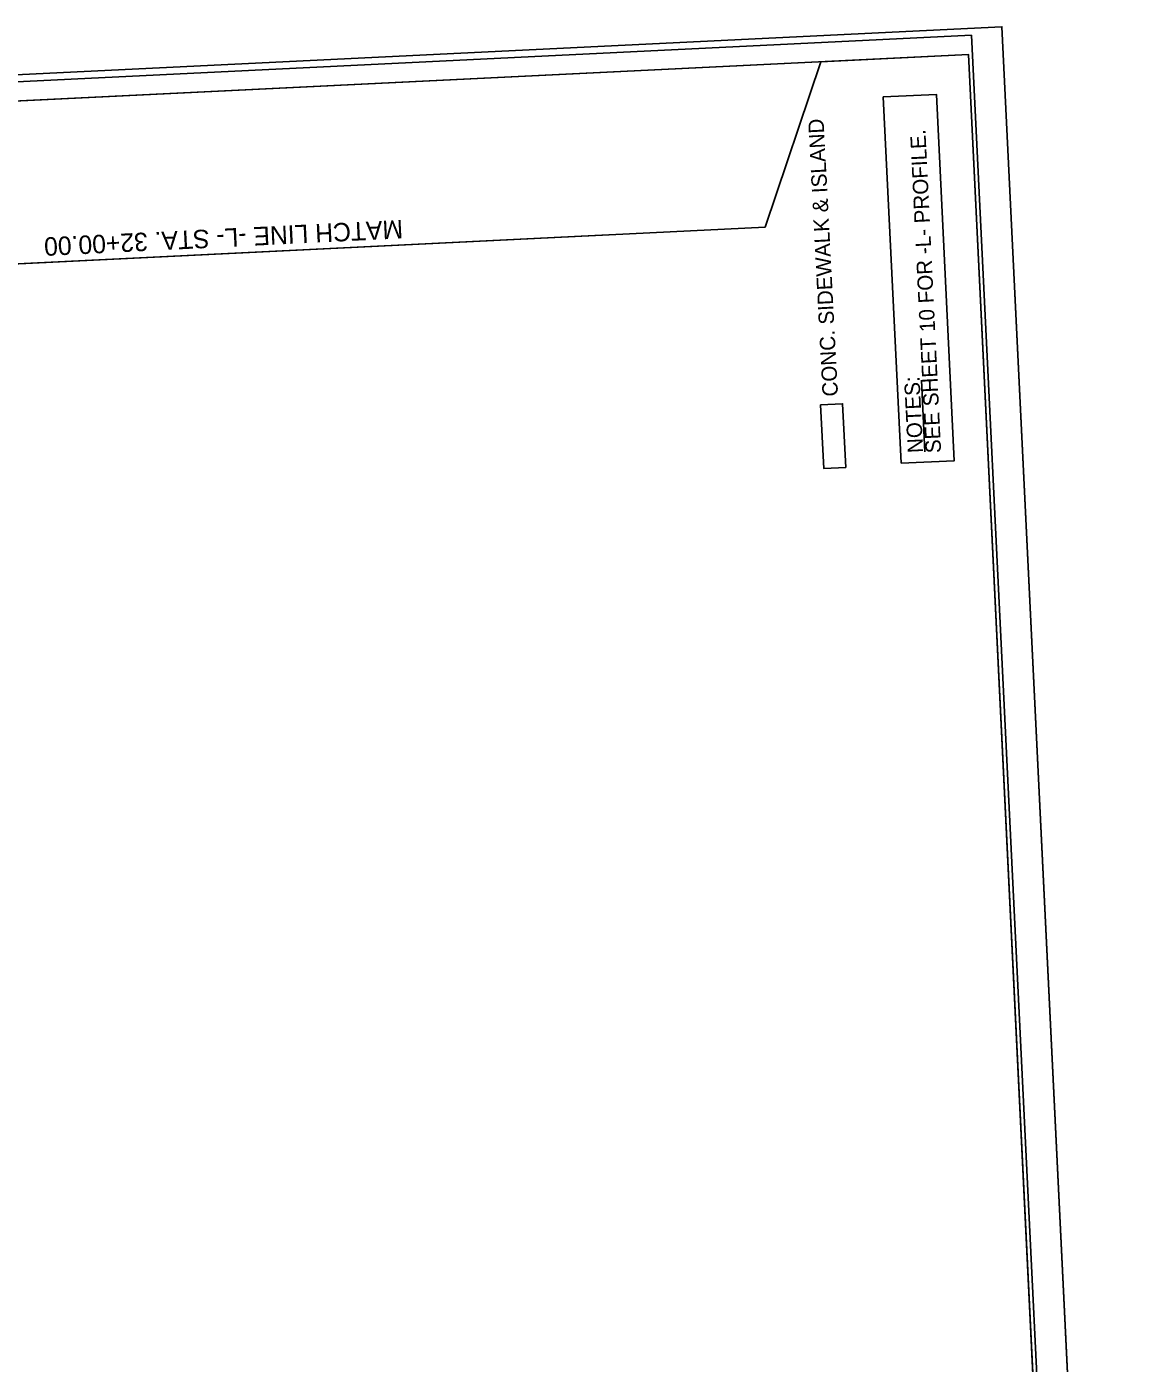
# Model space of a CAD drawing. Extents: x 2368277 to 2369452, y 801942 to 803676.
# Drawn here: x 2368738 to 2369452, y 802809 to 803676 of the extents above; entities that cross this region are included whole.
import ezdxf

# ---------------------------------------------------------------- set-up
doc = ezdxf.new("R2010")
doc.units = 0
for name, color, linetype in [('Old_Level_10', 7, 'Continuous'), ('Old_Level_15', 7, 'Continuous'), ('Old_Level_18', 7, 'Continuous'), ('Old_Level_2', 7, 'Continuous'), ('Old_Level_4', 7, 'Continuous'), ('Old_Level_5', 7, 'Continuous'), ('Old_Level_6', 7, 'Continuous'), ('Old_Level_62', 7, 'Continuous'), ('Old_Level_9', 7, 'Continuous'), ('Plot Label CELL', 7, 'Continuous'), ('Plot Shape CELL', 7, 'Continuous')]:
    doc.layers.add(name, color=color, linetype=linetype)

msp = doc.modelspace()

# ---------------------------------------------------------------- linework, layer by layer
at = {"layer": 'Old_Level_10'}
msp.add_lwpolyline([(2368373.13, 802108.95), (2369421.86, 802160.14), (2369348.77, 803658.36), (2368511.25, 803617.5), (2368522.91, 803378.54), (2368311.67, 803368.23)], close=True, dxfattribs=at)
at = {"layer": 'Old_Level_15'}
msp.add_line((2369452.45, 801994.95), (2369370.42, 803676.45), dxfattribs=at)
at = {"layer": 'Old_Level_18'}
msp.add_line((2369115.17, 803541.41), (2368609.24, 803516.53), dxfattribs=at)
at = {"layer": 'Old_Level_2'}
msp.add_lwpolyline([(2369296.9, 802302.46), (2369299.46, 802249.75), (2368368.59, 802201.94), (2368311.67, 803368.23), (2368522.91, 803378.54), (2368516.4, 803511.97), (2369216.72, 803546.4), (2369252.92, 803653.7), (2369348.77, 803658.37), (2369414.6, 802308.91)], close=True, dxfattribs=at)
msp.add_lwpolyline([(2369296.9, 802302.46), (2369299.46, 802249.75), (2368368.59, 802201.94), (2368311.67, 803368.23), (2368522.91, 803378.54), (2368516.4, 803511.97), (2369216.72, 803546.4), (2369252.92, 803653.7), (2369348.77, 803658.37), (2369414.6, 802308.91)], close=True, dxfattribs=at)
at = {"layer": 'Old_Level_4'}
msp.add_lwpolyline([(2369431.84, 802006.96), (2369350.65, 803670.97), (2368296.92, 803619.57), (2368378.1, 801955.55)], close=True, dxfattribs=at)
at = {"layer": 'Old_Level_5'}
msp.add_lwpolyline([(2369269.06, 803390.47), (2369267.05, 803431.74), (2369252.79, 803431.05), (2369254.81, 803389.77), (2369269.06, 803390.47)], dxfattribs=at)
at = {"layer": 'Old_Level_6'}
msp.add_lwpolyline([(2369452.45, 801994.95), (2369370.42, 803676.45), (2368276.72, 803623.09), (2368358.75, 801941.59)], close=True, dxfattribs=at)
at = {"layer": 'Old_Level_9'}
msp.add_lwpolyline([(2369269.06, 803390.47), (2369267.05, 803431.74), (2369252.79, 803431.05), (2369254.81, 803389.77), (2369269.06, 803390.47)], dxfattribs=at)
at = {"layer": 'Plot Label CELL'}
msp.add_line((2369320.5, 803400.55), (2369318.23, 803446.99), dxfattribs=at)
msp.add_lwpolyline([(2369305, 803393.12), (2369293.4, 803630.86), (2369327.97, 803632.54), (2369339.56, 803394.8)], close=True, dxfattribs=at)
at = {"layer": 'Plot Shape CELL'}
for points in [[(2368300.01, 803607.23), (2368373.1, 802108.98), (2369421.86, 802160.14), (2369348.77, 803658.37)], [(2369421.86, 802160.14), (2368373.13, 802108.95), (2368309.75, 803407.4), (2368459.63, 803414.72), (2368449.9, 803614.52), (2369348.77, 803658.37)]]:
    msp.add_lwpolyline(points, close=True, dxfattribs=at)

# ---------------------------------------------------------------- texts
at = {"layer": 'Old_Level_62'}
msp.add_text('MATCH LINE -L- STA. 32+00.00', height=12, rotation=182.8145, dxfattribs=at).set_placement((2368981.44, 803551.12))
at = {"layer": 'Plot Label CELL'}
for s, rotation, p in [('CONC. SIDEWALK & ISLAND', 92.998, (2369264.1, 803436.7)), ('SEE SHEET 10 FOR -L- PROFILE.', 92.79291, (2369331.02, 803399.93)), ('NOTES:', 92.79291, (2369319.34, 803400.03))]:
    msp.add_text(s, height=10, rotation=rotation, dxfattribs=at).set_placement(p)

doc.saveas('drawing.dxf')
